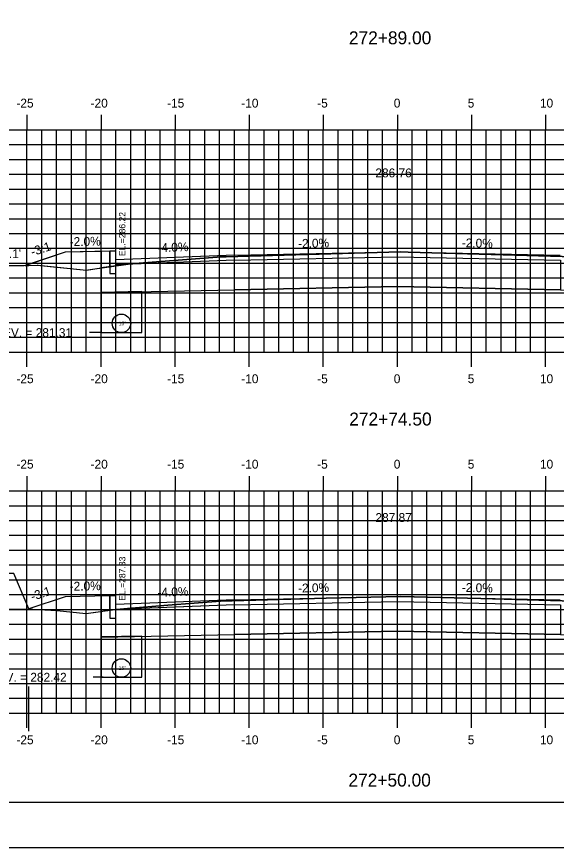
# Model space of a CAD drawing. Extents: x 852672 to 852842, y 366268 to 366378.
# Drawn here: x 852729.4 to 852765.8, y 366268.2 to 366324.2 of the extents above; entities that cross this region are included whole.
import ezdxf

# ---------------------------------------------------------------- set-up
doc = ezdxf.new("R2010")
doc.units = 0
for name, color, linetype in [('ANNOTATION', 7, 'Continuous'), ('BORDER', 7, 'Continuous'), ('D_Curb_Type_1_Lt', 7, 'Continuous'), ('D_Roadway_Centerline_Text', 7, 'Continuous'), ('D_Roadway_Edge_Shoulder', 7, 'Continuous'), ('D_Roadway_FinishedGrade', 7, 'Continuous'), ('D_Roadway_SubGrade', 7, 'Continuous'), ('D_Text_Standard', 7, 'Continuous'), ('H_V ANNOTATION', 7, 'Continuous'), ('JUNK COM EXC', 7, 'Continuous'), ('JUNK FILL', 7, 'Continuous'), ('junk strct exc', 7, 'Continuous'), ('MAJOR', 7, 'Continuous'), ('MINOR', 7, 'Continuous'), ('PDRAIN', 7, 'Continuous'), ('PLOT BOUNDARY', 7, 'Continuous'), ('S_Roadway_Centerline', 7, 'Continuous')]:
    doc.layers.add(name, color=color, linetype=linetype)

msp = doc.modelspace()

# ---------------------------------------------------------------- linework, layer by layer
at = {"layer": 'ANNOTATION'}
msp.add_line((852730.214, 366276.023), (852730.214, 366279.023), dxfattribs=at)
at = {"layer": 'BORDER'}
msp.add_line((852680.097, 366271.236), (852840.097, 366271.236), dxfattribs=at)
at = {"layer": 'D_Curb_Type_1_Lt'}
for points in [[(852735.68, 366308.402), (852735.68, 366306.902), (852736.096, 366306.902), (852736.096, 366308.402)], [(852735.68, 366285.147), (852735.68, 366283.647), (852736.096, 366283.647), (852736.096, 366285.147)]]:
    msp.add_lwpolyline(points, close=True, dxfattribs=at)
at = {"layer": 'D_Roadway_Edge_Shoulder'}
for p, q in [((852744.096, 366308.139), (852736.096, 366307.819)), ((852744.096, 366284.883), (852736.096, 366284.563)), ((852744.11, 366284.55), (852736.11, 366284.23))]:
    msp.add_line(p, q, dxfattribs=at)
for points in [[(852744.096, 366308.139), (852755.096, 366308.359), (852766.096, 366308.139)], [(852744.096, 366284.883), (852755.096, 366285.103), (852766.096, 366284.883)]]:
    msp.add_lwpolyline(points, dxfattribs=at)
at = {"layer": 'D_Roadway_FinishedGrade'}
for points in [[(852735.68, 366308.402), (852732.68, 366308.342)], [(852732.68, 366308.342), (852729.974, 366307.44)], [(852732.68, 366285.087), (852730.214, 366284.265)], [(852735.68, 366285.147), (852732.68, 366285.087)]]:
    msp.add_lwpolyline(points, dxfattribs=at)
at = {"layer": 'D_Roadway_SubGrade'}
for points in [[(852735.096, 366308.39), (852735.096, 366305.626)], [(852735.096, 366305.626), (852744.103, 366305.806), (852744.103, 366307.806), (852736.103, 366307.486)], [(852735.096, 366285.135), (852735.096, 366282.37)], [(852735.096, 366282.37), (852744.103, 366282.55), (852744.103, 366284.55), (852736.103, 366284.23)]]:
    msp.add_lwpolyline(points, dxfattribs=at)
for points in [[(852744.103, 366305.806), (852744.103, 366307.806), (852755.103, 366308.026), (852766.103, 366307.806), (852766.103, 366305.806), (852755.103, 366306.026)], [(852744.103, 366282.55), (852744.103, 366284.55), (852755.103, 366284.77), (852766.103, 366284.55), (852766.103, 366282.55), (852755.103, 366282.77)]]:
    msp.add_lwpolyline(points, close=True, dxfattribs=at)
at = {"layer": 'D_Text_Standard'}
for points in [[(852735.096, 366302.912), (852734.998, 366302.912), (852734.318, 366302.912)], [(852730.214, 366284.265), (852729.202, 366286.663), (852728.522, 366286.663)], [(852735.096, 366279.656), (852735.238, 366279.656), (852734.558, 366279.656)]]:
    msp.add_lwpolyline(points, dxfattribs=at)
at = {"layer": 'JUNK COM EXC'}
for points in [[(852735.096, 366307.276), (852735.096, 366305.626), (852744.103, 366305.806), (852755.103, 366306.026), (852766.103, 366305.806), (852775.096, 366305.625), (852775.096, 366307.795), (852770.534, 366307.914), (852769.515, 366307.943), (852768.631, 366307.978), (852755.835, 366308.343), (852755.304, 366308.357), (852743.535, 366308.037), (852743.147, 366308.03), (852742.933, 366308.015), (852737.092, 366307.564)], [(852735.096, 366284.093), (852735.096, 366282.37), (852744.103, 366282.55), (852755.103, 366282.77), (852766.103, 366282.55), (852775.096, 366282.37), (852775.096, 366284.495), (852768.567, 366284.754), (852760.727, 366284.977), (852755.337, 366285.113), (852750.296, 366284.984), (852743.148, 366284.793), (852739.613, 366284.517), (852736.872, 366284.298), (852735.862, 366284.203)]]:
    msp.add_lwpolyline(points, close=True, dxfattribs=at)
at = {"layer": 'JUNK FILL'}
msp.add_lwpolyline([(852735.096, 366307.276), (852735.68, 366307.36), (852735.68, 366308.402), (852735.096, 366308.39), (852732.68, 366308.342), (852730.214, 366307.52), (852729.974, 366307.44), (852730.217, 366307.453), (852730.784, 366307.475), (852734.112, 366307.134), (852735.096, 366307.276)], dxfattribs=at)
msp.add_lwpolyline([(852735.68, 366284.177), (852735.68, 366285.147), (852732.68, 366285.087), (852730.214, 366284.265), (852730.5, 366284.261), (852732.107, 366284.155), (852734.099, 366283.95)], close=True, dxfattribs=at)
at = {"layer": 'junk strct exc'}
for points in [[(852735.096, 366305.631), (852735.096, 366302.912), (852737.846, 366302.912), (852737.846, 366305.686)], [(852735.096, 366282.375), (852735.096, 366279.656), (852737.846, 366279.656), (852737.846, 366282.43)]]:
    msp.add_lwpolyline(points, close=True, dxfattribs=at)
at = {"layer": 'MAJOR'}
for p, q in [((852730.096, 366317.604), (852730.096, 366316.602)), ((852735.096, 366317.604), (852735.096, 366316.602)), ((852740.096, 366317.604), (852740.096, 366316.602)), ((852745.096, 366317.604), (852745.096, 366316.602)), ((852750.096, 366317.604), (852750.096, 366316.602)), ((852755.096, 366317.604), (852755.096, 366316.602)), ((852760.096, 366317.604), (852760.096, 366316.602)), ((852765.096, 366317.604), (852765.096, 366316.602)), ((852685.096, 366316.602), (852825.096, 366316.602)), ((852685.096, 366316.602), (852825.096, 366316.602)), ((852730.096, 366301.602), (852730.096, 366316.602)), ((852735.096, 366301.602), (852735.096, 366316.602)), ((852740.096, 366301.602), (852740.096, 366316.602)), ((852745.096, 366301.602), (852745.096, 366316.602)), ((852750.096, 366301.602), (852750.096, 366316.602)), ((852755.096, 366301.602), (852755.096, 366316.602)), ((852760.096, 366301.602), (852760.096, 366316.602)), ((852765.096, 366301.602), (852765.096, 366316.602)), ((852685.096, 366311.602), (852825.096, 366311.602)), ((852685.096, 366306.602), (852825.096, 366306.602)), ((852685.096, 366301.602), (852825.096, 366301.602)), ((852685.096, 366301.602), (852825.096, 366301.602)), ((852730.096, 366300.6), (852730.096, 366301.602)), ((852735.096, 366300.6), (852735.096, 366301.602)), ((852740.096, 366300.6), (852740.096, 366301.602)), ((852745.096, 366300.6), (852745.096, 366301.602)), ((852750.096, 366300.6), (852750.096, 366301.602)), ((852755.096, 366300.6), (852755.096, 366301.602)), ((852760.096, 366300.6), (852760.096, 366301.602)), ((852765.096, 366300.6), (852765.096, 366301.602)), ((852730.096, 366293.238), (852730.096, 366292.236)), ((852735.096, 366293.238), (852735.096, 366292.236)), ((852740.096, 366293.238), (852740.096, 366292.236)), ((852745.096, 366293.238), (852745.096, 366292.236)), ((852750.096, 366293.238), (852750.096, 366292.236)), ((852755.096, 366293.238), (852755.096, 366292.236)), ((852760.096, 366293.238), (852760.096, 366292.236)), ((852765.096, 366293.238), (852765.096, 366292.236)), ((852685.096, 366292.236), (852825.096, 366292.236)), ((852685.096, 366292.236), (852825.096, 366292.236)), ((852730.096, 366277.236), (852730.096, 366292.236)), ((852735.096, 366277.236), (852735.096, 366292.236)), ((852740.096, 366277.236), (852740.096, 366292.236)), ((852745.096, 366277.236), (852745.096, 366292.236)), ((852750.096, 366277.236), (852750.096, 366292.236)), ((852755.096, 366277.236), (852755.096, 366292.236)), ((852760.096, 366277.236), (852760.096, 366292.236)), ((852765.096, 366277.236), (852765.096, 366292.236)), ((852685.096, 366287.236), (852825.096, 366287.236)), ((852685.096, 366282.236), (852825.096, 366282.236)), ((852685.096, 366277.236), (852825.096, 366277.236)), ((852730.096, 366276.234), (852730.096, 366277.236)), ((852735.096, 366276.234), (852735.096, 366277.236)), ((852740.096, 366276.234), (852740.096, 366277.236)), ((852745.096, 366276.234), (852745.096, 366277.236)), ((852750.096, 366276.234), (852750.096, 366277.236)), ((852755.096, 366276.234), (852755.096, 366277.236)), ((852760.096, 366276.234), (852760.096, 366277.236)), ((852765.096, 366276.234), (852765.096, 366277.236))]:
    msp.add_line(p, q, dxfattribs=at)
at = {"layer": 'MINOR'}
for p, q in [((852731.096, 366301.602), (852731.096, 366316.602)), ((852732.096, 366301.602), (852732.096, 366316.602)), ((852733.096, 366301.602), (852733.096, 366316.602)), ((852734.096, 366301.602), (852734.096, 366316.602)), ((852736.096, 366301.602), (852736.096, 366316.602)), ((852737.096, 366301.602), (852737.096, 366316.602)), ((852738.096, 366301.602), (852738.096, 366316.602)), ((852739.096, 366301.602), (852739.096, 366316.602)), ((852741.096, 366301.602), (852741.096, 366316.602)), ((852742.096, 366301.602), (852742.096, 366316.602)), ((852743.096, 366301.602), (852743.096, 366316.602)), ((852744.096, 366301.602), (852744.096, 366316.602)), ((852746.096, 366301.602), (852746.096, 366316.602)), ((852747.096, 366301.602), (852747.096, 366316.602)), ((852748.096, 366301.602), (852748.096, 366316.602)), ((852749.096, 366301.602), (852749.096, 366316.602)), ((852751.096, 366301.602), (852751.096, 366316.602)), ((852752.096, 366301.602), (852752.096, 366316.602)), ((852753.096, 366301.602), (852753.096, 366316.602)), ((852754.096, 366301.602), (852754.096, 366316.602)), ((852756.096, 366301.602), (852756.096, 366316.602)), ((852757.096, 366301.602), (852757.096, 366316.602)), ((852758.096, 366301.602), (852758.096, 366316.602)), ((852759.096, 366301.602), (852759.096, 366316.602)), ((852761.096, 366301.602), (852761.096, 366316.602)), ((852762.096, 366301.602), (852762.096, 366316.602)), ((852763.096, 366301.602), (852763.096, 366316.602)), ((852764.096, 366301.602), (852764.096, 366316.602)), ((852685.096, 366315.602), (852825.096, 366315.602)), ((852685.096, 366314.602), (852825.096, 366314.602)), ((852685.096, 366313.602), (852825.096, 366313.602)), ((852685.096, 366312.602), (852825.096, 366312.602)), ((852685.096, 366310.602), (852825.096, 366310.602)), ((852685.096, 366309.602), (852825.096, 366309.602)), ((852685.096, 366308.602), (852825.096, 366308.602)), ((852685.096, 366307.602), (852825.096, 366307.602)), ((852685.096, 366305.602), (852825.096, 366305.602)), ((852685.096, 366304.602), (852825.096, 366304.602)), ((852685.096, 366303.602), (852825.096, 366303.602)), ((852685.096, 366302.602), (852825.096, 366302.602)), ((852731.096, 366277.236), (852731.096, 366292.236)), ((852732.096, 366277.236), (852732.096, 366292.236)), ((852733.096, 366277.236), (852733.096, 366292.236)), ((852734.096, 366277.236), (852734.096, 366292.236)), ((852736.096, 366277.236), (852736.096, 366292.236)), ((852737.096, 366277.236), (852737.096, 366292.236)), ((852738.096, 366277.236), (852738.096, 366292.236)), ((852739.096, 366277.236), (852739.096, 366292.236)), ((852741.096, 366277.236), (852741.096, 366292.236)), ((852742.096, 366277.236), (852742.096, 366292.236)), ((852743.096, 366277.236), (852743.096, 366292.236)), ((852744.096, 366277.236), (852744.096, 366292.236)), ((852746.096, 366277.236), (852746.096, 366292.236)), ((852747.096, 366277.236), (852747.096, 366292.236)), ((852748.096, 366277.236), (852748.096, 366292.236)), ((852749.096, 366277.236), (852749.096, 366292.236)), ((852751.096, 366277.236), (852751.096, 366292.236)), ((852752.096, 366277.236), (852752.096, 366292.236)), ((852753.096, 366277.236), (852753.096, 366292.236)), ((852754.096, 366277.236), (852754.096, 366292.236)), ((852756.096, 366277.236), (852756.096, 366292.236)), ((852757.096, 366277.236), (852757.096, 366292.236)), ((852758.096, 366277.236), (852758.096, 366292.236)), ((852759.096, 366277.236), (852759.096, 366292.236)), ((852761.096, 366277.236), (852761.096, 366292.236)), ((852762.096, 366277.236), (852762.096, 366292.236)), ((852763.096, 366277.236), (852763.096, 366292.236)), ((852764.096, 366277.236), (852764.096, 366292.236)), ((852685.096, 366291.236), (852825.096, 366291.236)), ((852685.096, 366290.236), (852825.096, 366290.236)), ((852685.096, 366289.236), (852825.096, 366289.236)), ((852685.096, 366288.236), (852825.096, 366288.236)), ((852685.096, 366286.236), (852825.096, 366286.236)), ((852685.096, 366285.236), (852825.096, 366285.236)), ((852685.096, 366284.236), (852825.096, 366284.236)), ((852685.096, 366283.236), (852825.096, 366283.236)), ((852685.096, 366281.236), (852825.096, 366281.236)), ((852685.096, 366280.236), (852825.096, 366280.236)), ((852685.096, 366279.236), (852825.096, 366279.236)), ((852685.096, 366278.236), (852825.096, 366278.236))]:
    msp.add_line(p, q, dxfattribs=at)
at = {"layer": 'PDRAIN'}
for points in [[(852735.096, 366305.626), (852735.096, 366302.912), (852737.846, 366302.912), (852737.846, 366305.681)], [(852735.096, 366282.37), (852735.096, 366279.656), (852737.846, 366279.656), (852737.846, 366282.425)]]:
    msp.add_lwpolyline(points, dxfattribs=at)
for centre in [(852736.471, 366303.537), (852736.471, 366280.281)]:
    msp.add_circle(centre, 0.625, dxfattribs=at)
at = {"layer": 'PLOT BOUNDARY'}
msp.add_lwpolyline([(852672.003, 366268.177), (852842.003, 366268.177), (852842.003, 366378.177), (852672.003, 366378.177)], close=True, dxfattribs=at)
at = {"layer": 'S_Roadway_Centerline'}
for points in [[(852728.866, 366307.44), (852729.91, 366307.44), (852730.784, 366307.475), (852730.859, 366307.473), (852734.112, 366307.134), (852734.197, 366307.146), (852737.092, 366307.564), (852742.933, 366308.015), (852743.147, 366308.03), (852743.535, 366308.037), (852755.304, 366308.357), (852755.835, 366308.343), (852768.631, 366307.978), (852769.515, 366307.943), (852770.534, 366307.914), (852776.806, 366307.75), (852781.253, 366307.615), (852788.243, 366307.882), (852797.252, 366308.252), (852804.718, 366308.433), (852813.271, 366308.593), (852814.799, 366308.574), (852816.079, 366308.529)], [(852724.924, 366284.328), (852730.5, 366284.261), (852732.107, 366284.155), (852734.099, 366283.95), (852735.862, 366284.203), (852736.872, 366284.298), (852739.613, 366284.517), (852743.148, 366284.793), (852750.296, 366284.984), (852755.337, 366285.113), (852760.727, 366284.977), (852768.567, 366284.754), (852777.674, 366284.393), (852781.547, 366284.279), (852781.713, 366284.526), (852781.906, 366284.604), (852782.399, 366284.612), (852783.022, 366284.502), (852789.054, 366284.547), (852792.363, 366284.537), (852796.447, 366284.629), (852805.26, 366284.798)]]:
    msp.add_lwpolyline(points, dxfattribs=at)

# ---------------------------------------------------------------- texts
at = {"layer": 'ANNOTATION'}
for s, rotation, p in [('-3:1', 18.4349, (852730.464, 366308.058)), ('-2.0%', 1.1458, (852732.983, 366308.748)), ('-4.0%', 2.2906, (852738.912, 366308.332)), ('-2.0%', 1.1458, (852748.4, 366308.625)), ('-2.0%', 1.1458, (852748.4, 366308.625)), ('-2.0%', 358.8542, (852759.44, 366308.672)), ('-2.0%', 358.8542, (852759.44, 366308.672)), ('-2.0%', 1.1458, (852732.983, 366285.493)), ('-2.0%', 1.1458, (852748.4, 366285.37)), ('-2.0%', 358.8542, (852759.44, 366285.417)), ('-3:1', 18.4349, (852730.464, 366284.802)), ('-4.0%', 2.2906, (852738.912, 366285.077))]:
    msp.add_text(s, height=0.6, rotation=rotation, dxfattribs=at).set_placement(p)
at = {"layer": 'D_Roadway_Centerline_Text'}
for s, p in [('286.76', (852753.614, 366313.391)), ('287.87', (852753.619, 366290.135))]:
    msp.add_text(s, height=0.6, dxfattribs=at).set_placement(p)
at = {"layer": 'D_Text_Standard'}
for s, p in [(' EL.=286.22', (852736.74, 366307.913)), (' EL.=287.33', (852736.74, 366284.657))]:
    msp.add_text(s, height=0.4335, rotation=90, dxfattribs=at).set_placement(p)
for s, p in [("-25.1'", (852727.716, 366307.939)), ('ELEV. = 281.31', (852727.496, 366302.612)), ('ELEV. = 282.42', (852727.131, 366279.356))]:
    msp.add_text(s, height=0.6, dxfattribs=at).set_placement(p)
at = {"layer": 'H_V ANNOTATION'}
for s, height, p in [('272+89.00', 0.875, (852751.827, 366322.37)), ('-25', 0.6, (852729.382, 366318.102)), ('-20', 0.6, (852734.39, 366318.102)), ('-15', 0.6, (852739.553, 366318.102)), ('-10', 0.6, (852744.561, 366318.102)), ('-5', 0.6, (852749.687, 366318.102)), ('0', 0.6, (852754.856, 366318.102)), ('5', 0.6, (852759.848, 366318.102)), ('10', 0.6, (852764.722, 366318.102)), ('-25', 0.6, (852729.382, 366299.502)), ('-20', 0.6, (852734.39, 366299.502)), ('-15', 0.6, (852739.553, 366299.502)), ('-10', 0.6, (852744.561, 366299.502)), ('-5', 0.6, (852749.687, 366299.502)), ('0', 0.6, (852754.856, 366299.502)), ('5', 0.6, (852759.848, 366299.502)), ('10', 0.6, (852764.722, 366299.502)), ('272+74.50', 0.875, (852751.85, 366296.645)), ('-25', 0.6, (852729.382, 366293.736)), ('-20', 0.6, (852734.39, 366293.736)), ('-15', 0.6, (852739.553, 366293.736)), ('-10', 0.6, (852744.561, 366293.736)), ('-5', 0.6, (852749.687, 366293.736)), ('0', 0.6, (852754.856, 366293.736)), ('5', 0.6, (852759.848, 366293.736)), ('10', 0.6, (852764.722, 366293.736)), ('-25', 0.6, (852729.382, 366275.136)), ('-20', 0.6, (852734.39, 366275.136)), ('-15', 0.6, (852739.553, 366275.136)), ('-10', 0.6, (852744.561, 366275.136)), ('-5', 0.6, (852749.687, 366275.136)), ('0', 0.6, (852754.856, 366275.136)), ('5', 0.6, (852759.848, 366275.136)), ('10', 0.6, (852764.722, 366275.136)), ('272+50.00', 0.875, (852751.795, 366272.28))]:
    msp.add_text(s, height=height, dxfattribs=at).set_placement(p)
at = {"layer": 'PDRAIN'}
for p in [(852736.284, 366303.412), (852736.284, 366280.156)]:
    msp.add_text('15"', height=0.25, dxfattribs=at).set_placement(p)
at = {"layer": 'S_Roadway_Centerline'}
for s, p in [('C', (852755.298, 366308.357)), ('L', (852755.304, 366308.35)), ('C', (852755.332, 366285.113)), ('L', (852755.337, 366285.106))]:
    msp.add_text(s, height=0.0146, dxfattribs=at).set_placement(p)

doc.saveas('drawing.dxf')
